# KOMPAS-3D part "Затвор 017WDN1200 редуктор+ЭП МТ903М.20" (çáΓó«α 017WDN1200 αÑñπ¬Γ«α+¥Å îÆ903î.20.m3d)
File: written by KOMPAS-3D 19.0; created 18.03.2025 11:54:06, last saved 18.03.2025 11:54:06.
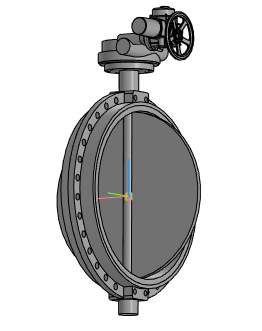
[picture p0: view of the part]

Document properties: Автор: Евгений; Полное имя файла: Затвор 017WDN1200 редуктор+ЭП МТ903М.20.a3d

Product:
- Part/product: Затвор 017WDN1200 редуктор+ЭП МТ903М.20
    Масса: 1356.26

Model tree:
1. Операция без истории:1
